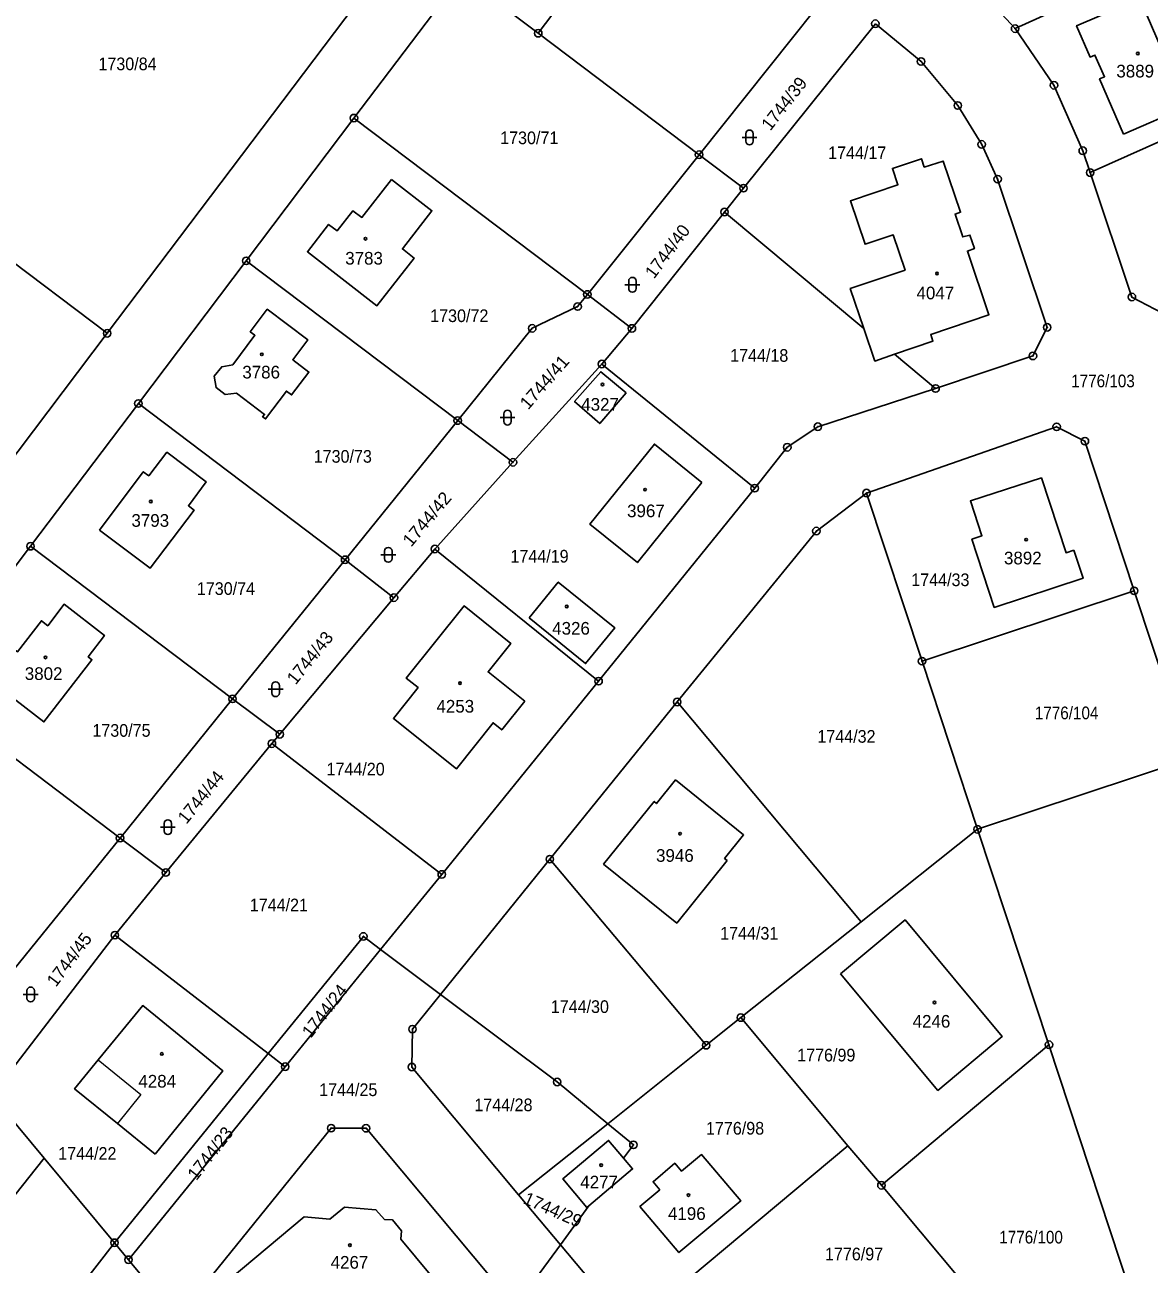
# Model space of a CAD drawing. Extents: x -679733 to -673243, y -1075091 to -1066557.
# Drawn here: x -677014 to -676863.1, y -1072506.6 to -1072340.3 of the extents above; entities that cross this region are included whole.
import ezdxf
from ezdxf.enums import TextEntityAlignment as Align

# ---------------------------------------------------------------- set-up
doc = ezdxf.new("R2010")
doc.units = 0
doc.header["$LTSCALE"] = 0.68
for name, color, linetype, lineweight in [('1', 7, 'Continuous', 25), ('3', 7, 'Continuous', 25), ('4', 7, 'Continuous', 13), ('5', 7, 'Continuous', 25), ('8', 7, 'Continuous', 25)]:
    doc.layers.add(name, color=color, linetype=linetype, lineweight=lineweight)
doc.layers.add('2', color=7, linetype='Continuous')

msp = doc.modelspace()

# ---------------------------------------------------------------- linework, layer by layer
at = {"layer": '1'}
for p, q in [((-676955.34, -1072333.67), (-676945.08, -1072341.44)), ((-677034.04, -1072358.2), (-677002.92, -1072381.7)), ((-676923.5, -1072357.73), (-676917.54, -1072362.22)), ((-676984.27, -1072371.97), (-676955.89, -1072393.41)), ((-676938.49, -1072376.48), (-676932.51, -1072381.04)), ((-676936.55, -1072385.82), (-676916.03, -1072402.47)), ((-676955.89, -1072393.41), (-676948.47, -1072399.01)), ((-676958.94, -1072410.64), (-676964.44, -1072417.17)), ((-676971, -1072412.08), (-676964.44, -1072417.17)), ((-676893.58, -1072425.69), (-676865.11, -1072416.25)), ((-676986.1, -1072430.75), (-676979.76, -1072435.5)), ((-676980.82, -1072436.75), (-676995.05, -1072454.05)), ((-676876.54, -1072477.15), (-676886.14, -1072448.25)), ((-677019.83, -1072472.45), (-677001.2, -1072449.42)), ((-677001.2, -1072449.42), (-676995.05, -1072454.05)), ((-676979.04, -1072480.1), (-676966.23, -1072464.36)), ((-676903.54, -1072490.7), (-676917.9, -1072473.51)), ((-676899.03, -1072496.01), (-676876.54, -1072477.15)), ((-676863.58, -1072516.59), (-676876.54, -1072477.15)), ((-677001.95, -1072503.72), (-676981.32, -1072478.34)), ((-676947.74, -1072497.31), (-676935.75, -1072487.75)), ((-676903.54, -1072490.7), (-676932.73, -1072515.13)), ((-677001.95, -1072503.72), (-677011.4, -1072492.35))]:
    msp.add_line(p, q, dxfattribs=at)
for points in [[(-677027.68, -1072429.42), (-677013.21, -1072410.27), (-676998.74, -1072391.12), (-676984.27, -1072371.97), (-676969.81, -1072352.82), (-676955.34, -1072333.67), (-676964.12, -1072327.04), (-676979.28, -1072315.59), (-676999.23, -1072300.52), (-677013.7, -1072319.67), (-677028.16, -1072338.82), (-677042.63, -1072357.97), (-677057.1, -1072377.12), (-677060.11, -1072381.11), (-677041.76, -1072394.98)], [(-676945.08, -1072341.44), (-676926.98, -1072317.5), (-676946.01, -1072303.12)], [(-677034.04, -1072358.2), (-676999.38, -1072312.31), (-676995.87, -1072311.82), (-676968.74, -1072332.31), (-676968.26, -1072335.81), (-677002.92, -1072381.7)], [(-676891.88, -1072330.24), (-676885.92, -1072335.57), (-676881.09, -1072340.82), (-676850.38, -1072326.91), (-676840.3, -1072323.62), (-676850.33, -1072316.37)], [(-676945.08, -1072341.44), (-676923.5, -1072357.73), (-676904.77, -1072334.29)], [(-676899.84, -1072340.16), (-676917.54, -1072362.22), (-676920.09, -1072365.43), (-676901.39, -1072381.05)], [(-676891.76, -1072389.1), (-676878.69, -1072384.73), (-676876.78, -1072380.9), (-676883.43, -1072361.01), (-676885.57, -1072356.35), (-676888.78, -1072351.13), (-676893.71, -1072345.23), (-676899.84, -1072340.16)], [(-676881.09, -1072340.82), (-676875.87, -1072348.42), (-676872.01, -1072357.2), (-676871.02, -1072360.14)], [(-676835.94, -1072370.6), (-676843.45, -1072347.81), (-676871.02, -1072360.14)], [(-676969.81, -1072352.82), (-676938.49, -1072376.48), (-676923.5, -1072357.73)], [(-677002.92, -1072381.7), (-677016.78, -1072400.05), (-677022.38, -1072400.83), (-677047.12, -1072382.15), (-677047.9, -1072376.55), (-677034.04, -1072358.2)], [(-676901.39, -1072381.05), (-676903.21, -1072375.69), (-676895.85, -1072373.21), (-676897.45, -1072368.5), (-676901.21, -1072369.76), (-676903.19, -1072363.93), (-676896.82, -1072361.77), (-676897.55, -1072359.57), (-676893.65, -1072358.28), (-676893.27, -1072359.4), (-676890.72, -1072358.59), (-676888.4, -1072365.45), (-676889.15, -1072365.71), (-676888.11, -1072368.77), (-676887.15, -1072368.51), (-676886.54, -1072370.34), (-676887.49, -1072370.67), (-676884.61, -1072379.2), (-676892.4, -1072381.84), (-676892.11, -1072382.76), (-676897.25, -1072384.51), (-676891.76, -1072389.1)], [(-676871.02, -1072360.14), (-676865.41, -1072376.83), (-676861.32, -1072378.99), (-676835.94, -1072370.6)], [(-676920.09, -1072365.43), (-676932.51, -1072381.04), (-676936.55, -1072385.82), (-676948.47, -1072399.01), (-676958.94, -1072410.64), (-676936.98, -1072428.37), (-676916.03, -1072402.47)], [(-676955.89, -1072393.41), (-676945.88, -1072381.03), (-676939.79, -1072378.11), (-676938.49, -1072376.48)], [(-676897.25, -1072384.51), (-676899.91, -1072385.42), (-676901.39, -1072381.05)], [(-676916.03, -1072402.47), (-676911.66, -1072396.99), (-676907.56, -1072394.23), (-676891.76, -1072389.1)], [(-676998.74, -1072391.12), (-676971, -1072412.08), (-676955.89, -1072393.41)], [(-676865.11, -1072416.25), (-676871.72, -1072396.17), (-676875.51, -1072394.24), (-676901.03, -1072403.13)], [(-676901.03, -1072403.13), (-676907.76, -1072408.23), (-676926.44, -1072431.16)], [(-676901.74, -1072460.64), (-676886.14, -1072448.25), (-676893.58, -1072425.69), (-676901.03, -1072403.13)], [(-677013.21, -1072410.27), (-676986.1, -1072430.75), (-676971, -1072412.08)], [(-676964.44, -1072417.17), (-676979.76, -1072435.5), (-676980.82, -1072436.75), (-676958.03, -1072454.3), (-676936.98, -1072428.37)], [(-676865.11, -1072416.25), (-676857.64, -1072438.81), (-676886.14, -1072448.25)], [(-677027.68, -1072429.42), (-677001.2, -1072449.42), (-676986.1, -1072430.75)], [(-676922.55, -1072477.22), (-676917.9, -1072473.51), (-676901.74, -1072460.64), (-676926.44, -1072431.16), (-676943.53, -1072452.25)], [(-676935.75, -1072487.75), (-676922.55, -1072477.22), (-676943.53, -1072452.25), (-676958.19, -1072470.4)], [(-676995.05, -1072454.05), (-677001.89, -1072462.45), (-676981.32, -1072478.34)], [(-676981.32, -1072478.34), (-676968.55, -1072462.62), (-676966.23, -1072464.36), (-676958.03, -1072454.3)], [(-677001.89, -1072462.45), (-677014.57, -1072478.97), (-677018.39, -1072483.95)], [(-676961.96, -1072475.06), (-676958.19, -1072470.4), (-676966.23, -1072464.36)], [(-676935.75, -1072487.75), (-676942.54, -1072482.15), (-676958.19, -1072470.4)], [(-676947.74, -1072497.31), (-676962.04, -1072480.14), (-676961.96, -1072475.06)], [(-677000.06, -1072506), (-676979.04, -1072480.1), (-676981.32, -1072478.34)], [(-676993.55, -1072513.87), (-676972.87, -1072488.34), (-676968.19, -1072488.36), (-676951.31, -1072508.5)], [(-676933.63, -1072492.39), (-676932.31, -1072490.58), (-676935.75, -1072487.75)], [(-676938.55, -1072498.98), (-676941.78, -1072495.15), (-676935.65, -1072490), (-676933.63, -1072492.39)], [(-676888.56, -1072508.51), (-676899.03, -1072496.01), (-676903.54, -1072490.7)], [(-676933.63, -1072492.39), (-676932.42, -1072493.82), (-676938.28, -1072498.75)], [(-676948.16, -1072512.28), (-676942.11, -1072504), (-676947.74, -1072497.31)], [(-676942.11, -1072504), (-676938.28, -1072498.75), (-676938.55, -1072498.98)], [(-676993.55, -1072513.87), (-677000.06, -1072506), (-677001.95, -1072503.72), (-677049.16, -1072564.49), (-677001.46, -1072586.15)], [(-676917.69, -1072532.9), (-676932.73, -1072515.13), (-676942.11, -1072504)]]:
    msp.add_lwpolyline(points, dxfattribs=at)
for points in [[(-676866.54, -1072354.96), (-676869.74, -1072347.57), (-676869.09, -1072347.28), (-676870.37, -1072344.36), (-676871.02, -1072344.64), (-676872.83, -1072340.44), (-676864.36, -1072336.78), (-676858.08, -1072351.31)], [(-676964.75, -1072361.04), (-676959.34, -1072365.25), (-676963.31, -1072370.37), (-676961.75, -1072371.61), (-676966.72, -1072378), (-676976.05, -1072370.76), (-676973.21, -1072367.09), (-676972.07, -1072367.96), (-676969.94, -1072365.25), (-676968.75, -1072366.15)], [(-676987.07, -1072389.9), (-676988.3, -1072388.98), (-676988.57, -1072387.45), (-676987.56, -1072386.19), (-676986.07, -1072385.93), (-676983.1, -1072381.96), (-676983.73, -1072381.5), (-676981.45, -1072378.47), (-676976.02, -1072382.57), (-676978.03, -1072385.25), (-676975.86, -1072386.91), (-676978.19, -1072389.96), (-676978.88, -1072389.45), (-676981.67, -1072393.18), (-676982.07, -1072392.9), (-676981.81, -1072392.59), (-676985.59, -1072389.73)], [(-676933.29, -1072389.68), (-676936.82, -1072393.8), (-676940.2, -1072390.86), (-676936.7, -1072386.85)], [(-676923.13, -1072401.7), (-676931.78, -1072412.45), (-676938.15, -1072407.32), (-676929.48, -1072396.56)], [(-677003.97, -1072408.09), (-676998.08, -1072400.28), (-676997.34, -1072400.82), (-676994.91, -1072397.66), (-676989.63, -1072401.63), (-676992.03, -1072404.84), (-676991.27, -1072405.43), (-676997.16, -1072413.21)], [(-676873.2, -1072410.8), (-676871.97, -1072414.56), (-676883.88, -1072418.47), (-676886.89, -1072409.32), (-676885.55, -1072408.87), (-676887.09, -1072404.19), (-676877.56, -1072401.1), (-676874.24, -1072411.14)], [(-676946.31, -1072419.89), (-676942.39, -1072415.08), (-676934.81, -1072421.2), (-676938.72, -1072426.02)], [(-677018.97, -1072428.02), (-677015.75, -1072423.84), (-677014.96, -1072424.44), (-677011.75, -1072420.27), (-677010.89, -1072420.93), (-677008.7, -1072418.05), (-677003.29, -1072422.23), (-677005.47, -1072425.12), (-677004.97, -1072425.5), (-677011.41, -1072433.85)], [(-676946.9, -1072431.06), (-676949.97, -1072434.92), (-676951.14, -1072433.96), (-676956.06, -1072440.14), (-676964.52, -1072433.37), (-676961.21, -1072429.24), (-676962.81, -1072427.96), (-676955.04, -1072418.27), (-676948.75, -1072423.33), (-676951.81, -1072427.12)], [(-676919.74, -1072452.43), (-676926.49, -1072460.82), (-676936.31, -1072452.91), (-676929.52, -1072444.51), (-676929.21, -1072444.8), (-676926.64, -1072441.62), (-676917.53, -1072449), (-676920.07, -1072452.16)], [(-676904.53, -1072467.63), (-676895.85, -1072460.4), (-676882.82, -1072476.03), (-676891.44, -1072483.28)], [(-676996.49, -1072491.85), (-677001.55, -1072487.73), (-677007.29, -1072483.05), (-677004.13, -1072479.17), (-676998.15, -1072471.9), (-676987.39, -1072480.67)], [(-677033.34, -1072502.73), (-677050.71, -1072525.09), (-677071.32, -1072551.51), (-677073, -1072553.66), (-677063.46, -1072557.99), (-677011.4, -1072492.35), (-677018.39, -1072483.95)], [(-676928.76, -1072496.61), (-676929.66, -1072495.54), (-676926.76, -1072493.06), (-676925.84, -1072494.12), (-676923.17, -1072491.88), (-676917.91, -1072498.1), (-676926.21, -1072505.03), (-676931.43, -1072498.86)], [(-676963.42, -1072502.11), (-676963.53, -1072503.25), (-676957.82, -1072510.06), (-676964.6, -1072515.73), (-676969.84, -1072509.45), (-676973.34, -1072509.15), (-676980.75, -1072515.32), (-676986.4, -1072508.54), (-676976.51, -1072500.25), (-676973.06, -1072500.55), (-676971.09, -1072498.94), (-676966.87, -1072499.3), (-676965.73, -1072500.58), (-676964.63, -1072500.65)]]:
    msp.add_lwpolyline(points, close=True, dxfattribs=at)
at = {"layer": '3'}
for p, q in [((-676917.731, -1072355.421), (-676915.729, -1072355.421)), ((-676917.231, -1072354.921), (-676917.231, -1072355.922)), ((-676916.229, -1072355.922), (-676916.229, -1072354.921)), ((-676933.441, -1072375.191), (-676931.439, -1072375.191)), ((-676932.941, -1072374.691), (-676932.941, -1072375.692)), ((-676931.939, -1072375.692), (-676931.939, -1072374.691)), ((-676949.701, -1072392.511), (-676949.701, -1072393.512)), ((-676948.699, -1072393.512), (-676948.699, -1072392.511)), ((-676950.201, -1072393.011), (-676948.199, -1072393.011)), ((-676966.201, -1072411.421), (-676964.199, -1072411.421)), ((-676965.701, -1072410.921), (-676965.701, -1072411.922)), ((-676964.699, -1072411.922), (-676964.699, -1072410.921)), ((-676980.821, -1072428.951), (-676980.821, -1072429.952)), ((-676979.819, -1072429.952), (-676979.819, -1072428.951)), ((-676981.321, -1072429.451), (-676979.319, -1072429.451)), ((-676995.781, -1072447.961), (-676993.779, -1072447.961)), ((-676995.281, -1072447.461), (-676995.281, -1072448.462)), ((-676994.279, -1072448.462), (-676994.279, -1072447.461)), ((-677014.191, -1072470.411), (-677012.189, -1072470.411)), ((-677013.691, -1072469.911), (-677013.691, -1072470.912)), ((-677012.689, -1072470.912), (-677012.689, -1072469.911))]:
    msp.add_line(p, q, dxfattribs=at)
for centre, start, end in [((-676916.73, -1072354.9209), 0, 180), ((-676916.73, -1072355.9209), 180, 359.98789), ((-676932.44, -1072374.6909), 0, 180), ((-676932.44, -1072375.6909), 180, 359.98789), ((-676949.2, -1072392.5109), 0, 180), ((-676949.2, -1072393.5109), 180, 359.98789), ((-676965.2, -1072410.9209), 0, 180), ((-676965.2, -1072411.9209), 180, 359.98789), ((-676980.32, -1072428.9509), 0, 180), ((-676980.32, -1072429.9509), 180, 359.98789), ((-676994.78, -1072447.4609), 0, 180), ((-676994.78, -1072448.4609), 180, 359.98789), ((-677013.19, -1072469.9109), 0, 180), ((-677013.19, -1072470.9109), 180, 359.98789)]:
    msp.add_arc(centre, 0.5, start, end, dxfattribs=at)
at = {"layer": '4'}
msp.add_lwpolyline([(-677004.13, -1072479.17), (-676998.39, -1072483.85), (-677001.55, -1072487.73)], dxfattribs=at)
at = {"layer": '5'}
for centre in [(-676864.6268, -1072344.1592), (-676968.2668, -1072369.0092), (-676891.5668, -1072373.6792), (-676982.1668, -1072384.5192), (-676936.4568, -1072388.5692), (-676930.7468, -1072402.6792), (-676997.0768, -1072404.2692), (-676879.5968, -1072409.3892), (-676941.2568, -1072418.3492), (-677011.2068, -1072425.1792), (-676955.5768, -1072428.6392), (-676926.0468, -1072448.8392), (-676891.9068, -1072471.4792), (-676995.5868, -1072478.3892), (-676936.6268, -1072493.2992), (-676924.9268, -1072497.3192), (-676970.3468, -1072504.0492)]:
    msp.add_circle(centre, 0.175, dxfattribs=at)
at = {"layer": '8'}
for centre, radius in [((-676945.08, -1072341.4399), 0.5), ((-676899.84, -1072340.1599), 0.5), ((-676881.09, -1072340.8199), 0.5), ((-676881.09, -1072340.8199), 0.0303), ((-676945.08, -1072341.4399), 0.0303), ((-676893.71, -1072345.2299), 0.5), ((-676893.71, -1072345.2299), 0.0303), ((-676875.87, -1072348.4199), 0.5), ((-676875.87, -1072348.4199), 0.0303), ((-676888.78, -1072351.1299), 0.5), ((-676969.81, -1072352.8199), 0.5), ((-676888.78, -1072351.1299), 0.0303), ((-676969.81, -1072352.8199), 0.0303), ((-676885.57, -1072356.3499), 0.5), ((-676923.5, -1072357.7299), 0.5), ((-676885.57, -1072356.3499), 0.0303), ((-676872.01, -1072357.1999), 0.5), ((-676872.01, -1072357.1999), 0.0303), ((-676923.5, -1072357.7299), 0.0303), ((-676883.43, -1072361.0099), 0.5), ((-676871.02, -1072360.1399), 0.5), ((-676871.02, -1072360.1399), 0.0303), ((-676917.54, -1072362.2199), 0.5), ((-676917.54, -1072362.2199), 0.0303), ((-676883.43, -1072361.0099), 0.0303), ((-676920.09, -1072365.4299), 0.5), ((-676920.09, -1072365.4299), 0.0303), ((-676984.27, -1072371.9699), 0.5), ((-676984.27, -1072371.9699), 0.0303), ((-676938.49, -1072376.4799), 0.5), ((-676938.49, -1072376.4799), 0.0303), ((-676865.41, -1072376.8299), 0.5), ((-676865.41, -1072376.8299), 0.0303), ((-676939.79, -1072378.1099), 0.5), ((-676939.79, -1072378.1099), 0.0303), ((-676945.88, -1072381.0299), 0.5), ((-676932.51, -1072381.0399), 0.5), ((-676876.78, -1072380.8999), 0.5), ((-676876.78, -1072380.8999), 0.0303), ((-677002.92, -1072381.6999), 0.5), ((-677002.92, -1072381.6999), 0.0303), ((-676945.88, -1072381.0299), 0.0303), ((-676932.51, -1072381.0399), 0.0303), ((-676936.55, -1072385.8199), 0.5), ((-676936.55, -1072385.8199), 0.0303), ((-676878.69, -1072384.7299), 0.5), ((-676878.69, -1072384.7299), 0.0303), ((-676891.76, -1072389.0999), 0.5), ((-676891.76, -1072389.0999), 0.0303), ((-676998.74, -1072391.1199), 0.5), ((-676998.74, -1072391.1199), 0.0303), ((-676955.89, -1072393.4099), 0.5), ((-676955.89, -1072393.4099), 0.0303), ((-676907.56, -1072394.2299), 0.5), ((-676875.51, -1072394.2399), 0.5), ((-676907.56, -1072394.2299), 0.0303), ((-676875.51, -1072394.2399), 0.0303), ((-676871.72, -1072396.1699), 0.5), ((-676911.66, -1072396.9899), 0.5), ((-676911.66, -1072396.9899), 0.0303), ((-676871.72, -1072396.1699), 0.0303), ((-676948.47, -1072399.0099), 0.5), ((-676948.47, -1072399.0099), 0.0303), ((-676916.03, -1072402.4699), 0.5), ((-676916.03, -1072402.4699), 0.0303), ((-676901.03, -1072403.1299), 0.5), ((-676901.03, -1072403.1299), 0.0303), ((-676907.76, -1072408.2299), 0.5), ((-676907.76, -1072408.2299), 0.0303), ((-677013.21, -1072410.2699), 0.5), ((-677013.21, -1072410.2699), 0.0303), ((-676958.94, -1072410.6399), 0.5), ((-676958.94, -1072410.6399), 0.0303), ((-676971, -1072412.0799), 0.5), ((-676971, -1072412.0799), 0.0303), ((-676865.11, -1072416.2499), 0.5), ((-676964.44, -1072417.1699), 0.5), ((-676964.44, -1072417.1699), 0.0303), ((-676865.11, -1072416.2499), 0.0303), ((-676893.58, -1072425.6899), 0.5), ((-676893.58, -1072425.6899), 0.0303), ((-676936.98, -1072428.3699), 0.5), ((-676936.98, -1072428.3699), 0.0303), ((-676986.1, -1072430.7499), 0.5), ((-676986.1, -1072430.7499), 0.0303), ((-676926.44, -1072431.1599), 0.5), ((-676926.44, -1072431.1599), 0.0303), ((-676979.76, -1072435.4999), 0.5), ((-676979.76, -1072435.4999), 0.0303), ((-676980.82, -1072436.7499), 0.5), ((-676980.82, -1072436.7499), 0.0303), ((-677001.2, -1072449.4199), 0.5), ((-676886.14, -1072448.2499), 0.5), ((-676886.14, -1072448.2499), 0.0303), ((-677001.2, -1072449.4199), 0.0303), ((-676943.53, -1072452.2499), 0.5), ((-676943.53, -1072452.2499), 0.0303), ((-676995.05, -1072454.0499), 0.5), ((-676995.05, -1072454.0499), 0.0303), ((-676958.03, -1072454.2999), 0.5), ((-676958.03, -1072454.2999), 0.0303), ((-677001.89, -1072462.4499), 0.5), ((-676968.55, -1072462.6199), 0.5), ((-677001.89, -1072462.4499), 0.0303), ((-676968.55, -1072462.6199), 0.0303), ((-676917.9, -1072473.5099), 0.5), ((-676917.9, -1072473.5099), 0.0303), ((-676961.96, -1072475.0599), 0.5), ((-676961.96, -1072475.0599), 0.0303), ((-676922.55, -1072477.2199), 0.5), ((-676922.55, -1072477.2199), 0.0303), ((-676876.54, -1072477.1499), 0.5), ((-676876.54, -1072477.1499), 0.0303), ((-676979.04, -1072480.0999), 0.5), ((-676979.04, -1072480.0999), 0.0303), ((-676962.04, -1072480.1399), 0.5), ((-676962.04, -1072480.1399), 0.0303), ((-676942.54, -1072482.1499), 0.5), ((-676942.54, -1072482.1499), 0.0303), ((-676972.87, -1072488.3399), 0.5), ((-676972.87, -1072488.3399), 0.0303), ((-676968.19, -1072488.3599), 0.5), ((-676968.19, -1072488.3599), 0.0303), ((-676932.31, -1072490.5799), 0.5), ((-676932.31, -1072490.5799), 0.0303), ((-676899.03, -1072496.0099), 0.5), ((-676899.03, -1072496.0099), 0.0303), ((-677001.95, -1072503.7199), 0.5), ((-677001.95, -1072503.7199), 0.0303), ((-677000.06, -1072505.9999), 0.5), ((-677000.06, -1072505.9999), 0.0303)]:
    msp.add_circle(centre, radius, dxfattribs=at)

# ---------------------------------------------------------------- texts
at = {"layer": '2'}
for s, width, p in [('1730/84', 0.95, (-677004.1, -1072346.4)), ('1730/71', 0.95, (-676950.19, -1072356.32)), ('1744/17', 0.95, (-676906.18, -1072358.33)), ('1730/72', 0.95, (-676959.58, -1072380.19)), ('1744/18', 0.95, (-676919.33, -1072385.519)), ('1776/103', 0.9, (-676873.56, -1072388.94)), ('1730/73', 0.95, (-676975.21, -1072399.06)), ('1744/19', 0.95, (-676948.81, -1072412.46)), ('1744/33', 0.95, (-676895.02, -1072415.62)), ('1730/74', 0.95, (-676990.89, -1072416.8)), ('1776/104', 0.9, (-676878.44, -1072433.479)), ('1730/75', 0.95, (-677004.91, -1072435.83)), ('1744/32', 0.95, (-676907.62, -1072436.63)), ('1744/20', 0.95, (-676973.49, -1072441.019)), ('1744/21', 0.95, (-676983.79, -1072459.249)), ('1744/31', 0.95, (-676920.67, -1072463.05)), ('1744/30', 0.95, (-676943.4, -1072472.89)), ('1776/99', 0.95, (-676910.33, -1072479.39)), ('1776/98', 0.95, (-676922.57, -1072489.21)), ('1744/22', 0.95, (-677009.49, -1072492.59)), ('1776/100', 0.9, (-676883.21, -1072503.82)), ('1776/97', 0.95, (-676906.6, -1072506.08))]:
    msp.add_text(s, height=1.7, dxfattribs=dict(at, width=width)).set_placement(p)
for s, p in [('3889', (-676867.5, -1072347.37)), ('3783', (-676970.98, -1072372.479)), ('3786', (-676984.79, -1072387.759)), ('3967', (-676933.16, -1072406.37)), ('3793', (-676999.67, -1072407.66)), ('3892', (-676882.58, -1072412.7)), ('3802', (-677013.98, -1072428.21)), ('3946', (-676929.27, -1072452.61)), ('4284', (-676998.74, -1072482.9))]:
    msp.add_text(s, height=1.7, dxfattribs=at).set_placement(p)
for s, rotation, p in [('1744/39', 52, (-676913.94, -1072354.633)), ('1744/40', 53, (-676929.541, -1072374.481)), ('1744/43', 51, (-676977.639, -1072428.954)), ('1744/44', 51, (-676992.289, -1072447.654)), ('1744/45', 53, (-677009.811, -1072469.511))]:
    msp.add_text(s, height=1.7, rotation=rotation, dxfattribs=at).set_placement(p)
for s, p in [('4047', (-676891.79, -1072377.14)), ('4327', (-676936.78, -1072392.08)), ('4326', (-676940.68, -1072422.13)), ('4253', (-676956.21, -1072432.59)), ('4246', (-676892.31, -1072474.86)), ('4277', (-676936.91, -1072496.43)), ('4196', (-676925.14, -1072500.66)), ('4267', (-676970.41, -1072507.2))]:
    msp.add_text(s, height=1.7, dxfattribs=at).set_placement(p, align=Align.CENTER)
at = {"layer": '2', "width": 1.05}
for s, rotation, p in [('1744/41', 49, (-676946.438, -1072392.057)), ('1744/42', 50, (-676962.138, -1072410.466))]:
    msp.add_text(s, height=1.7, rotation=rotation, dxfattribs=at).set_placement(p)
at = {"layer": '2'}
for s, rotation, p in [('1744/24', 52, (-676973.0672, -1072473.1233)), ('1744/23', 52, (-676988.4272, -1072492.2333)), ('1744/29', 336, (-676943.4652, -1072500.0587))]:
    msp.add_text(s, height=1.7, rotation=rotation, dxfattribs=at).set_placement(p, align=Align.CENTER)
at = {"layer": '2', "width": 0.95}
for s, p in [('1744/25', (-676970.57, -1072484.04)), ('1744/28', (-676949.75, -1072486.07))]:
    msp.add_text(s, height=1.7, dxfattribs=at).set_placement(p, align=Align.CENTER)

doc.saveas('drawing.dxf')
